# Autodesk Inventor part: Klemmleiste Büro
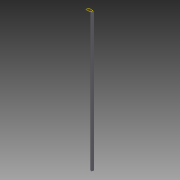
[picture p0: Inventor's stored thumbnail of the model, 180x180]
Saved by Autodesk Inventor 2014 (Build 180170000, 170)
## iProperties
Created: 2013-09
Part Number: Klemmleiste Büro
Material: Generisch
Document SubType Name: Modeling
Designer: Stefan Tammegger
Density: 1 g/cm^3
Appearance: Vorgabe
Author: Stefan Tammegger
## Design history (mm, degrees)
node "Blöcke"
  sketch "Glasklemmleiste unten"
    geometry: L1 (-60.068, 49.16)-(-60.068, 109.16); L2 (-60.068, 109.16)-(-63.068, 109.16); L3 (-60.068, 49.16)-(-63.068, 49.16); L4 (-63.068, 74.16)-(-67.068, 74.16); L5 (-67.068, 74.16)-(-67.068, 75.66); L6 (-67.068, 75.66)-(-63.068, 75.66); L7 (-63.068, 49.16)-(-63.068, 74.16); L8 (-60.068, 79.16)-(-63.068, 79.16); L9 (-63.068, 84.16)-(-67.068, 84.16); L10 (-67.068, 84.16)-(-67.068, 82.66); L11 (-67.068, 82.66)-(-63.068, 82.66); L12 (-63.068, 75.66)-(-63.068, 82.66); L13 (-63.068, 84.16)-(-63.068, 109.16); 1 further point
    constraints: 26 end point, 5 perpendicular, 4 symmetric about line, 1 coincident, 1 midpoint, 1 parallel
    dimensions: "d0" = 60 distance of L1.start L1.end; "d1" = 3 distance of L1.end L2.end; "d2" = 3 distance of L1.start L3.end; "d3" = 4 distance of L4.start L4.end; "d4" = 1.5 distance of L4.end L5.end; "d5" = 25 distance between parallel lines of L3 L4
  sketch "Glasklemmleiste oben"
    geometry: L1 (-37.726, 59.874)-(-30.726, 59.874); L2 (-30.726, 119.874)-(-37.726, 119.874); L3 (-39.726, 117.874)-(-39.726, 61.874); L4 (-30.726, 59.874)-(-30.726, 74.874); L5 (-30.726, 119.874)-(-30.726, 104.874); L6 (-38.226, 74.874)-(-38.226, 104.874); L7 (-30.726, 74.874)-(-38.226, 74.874); L8 (-30.726, 104.874)-(-38.226, 104.874); L9 (-30.726, 119.874)-(-24.726, 119.874); L10 (-24.726, 119.874)-(-24.726, 104.874); L11 (-24.726, 104.874)-(-30.726, 104.874); L12 (-30.726, 59.874)-(-24.726, 59.874); L13 (-24.726, 59.874)-(-24.726, 74.874); L14 (-24.726, 74.874)-(-30.726, 74.874); L15 (-38.226, 61.374)-(-26.226, 61.374); L16 (-26.226, 61.374)-(-26.226, 73.374); L17 (-26.226, 73.374)-(-38.226, 73.374); L18 (-38.226, 73.374)-(-38.226, 61.374); L19 (-38.226, 106.374)-(-26.226, 106.374); L20 (-26.226, 106.374)-(-26.226, 118.374); L21 (-26.226, 118.374)-(-38.226, 118.374); L22 (-38.226, 118.374)-(-38.226, 106.374); A1 r 2 centre (-37.726, 61.874) between (-39.726, 61.874) and (-37.726, 59.874); A2 r 2 centre (-37.726, 117.874) between (-37.726, 119.874) and (-39.726, 117.874); 2 further points
    constraints: 44 end point, 10 parallel, 5 perpendicular, 4 point on circle, 4 tangent, 3 horizontal, 2 centre point, 2 point on line, 1 collinear, 1 equal radius, 1 midpoint
    dimensions: "d6" = 9 distance of point (-39.726, 119.874) L2.start; "d7" = 60 distance of L2.start L1.end; "d8" = 15 distance of L1.end L4.end; "d9" = 15 distance of L2.start L5.end; "d10" = 1.5 distance between parallel lines of L3 L6; "d11" = 6 distance of L2.start L9.end; "d12" = 6 distance of L1.end L12.end; "d13" = 1.5 distance between parallel lines of L13 L16; "d14" = 1.5 distance between parallel lines of L1 L15; "d15" = 1.5 distance between parallel lines of L3 L18; "d16" = 1.5 distance between parallel lines of L7 L17; "d17" = 1.5 distance between parallel lines of L8 L19; "d18" = 1.5 distance between parallel lines of L10 L20; "d19" = 1.5 distance between parallel lines of L2 L21; "d20" = 1.5 distance between parallel lines of L3 L22; "d21" = 2 radius of A1
workplane "Arbeitsebene1"
sketch "Skizze1"
  geometry: L1 (50, -26)-(50, 26) reference; 1 further point
  constraints: 1 vertical
  node "Referenz1"
  node "Glasklemmleiste unten:1"
workplane "Arbeitsebene2"
extrude "Extrusion1" new body sketch "Skizze1" stored distance "d22" = 10; taper "d23" = 0 deg
sketch "Skizze2"
  geometry: L1 (53, 30)-(50, 30) reference; L2 (53, 5)-(53, 30) reference; 1 further point
  constraints: 1 horizontal
  dimensions: "d24" = 14 dimension on L2
extrude "Extrusion2" new body sketch "Skizze2" stored distance "d25" = 10; taper "d26" = 0 deg
sketch "Skizze3" dims "d35" = 10
  geometry: L1 (0, 0)-(3429.82, 0) reference; L2 (0, -56)-(0, 0) reference; L3 (0, -43)-(3419.21, -43) reference; 9 further points
  constraints: 1 horizontal, 7 other
  dimensions: "d28" = 50 distance from line of L2 point (50, -28); "d29" = 28 distance from line of L1 point (50, -28); "d32" = 470 distance of point (50, -28) point (520, -28)
hole "Bohrung1" sketch "Skizze3" at (50, -28), (520, -28), (990, -28), (1460, -28), (1930, -28), (2400, -28), (2870, -28), (3340, -28) diameter "d37" = 6; stored, may be unused: countersink angle "d41" = 90 deg, drill point angle "d43" = 118 deg; dims "d38" = 6, "d39" = 4, "d40" = 2, "d42" = 8
node "Volumenkörper1"
node "Volumenkörper2"
node "Glasklemmleiste oben:1" dims "d24" = 14
